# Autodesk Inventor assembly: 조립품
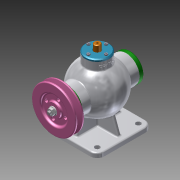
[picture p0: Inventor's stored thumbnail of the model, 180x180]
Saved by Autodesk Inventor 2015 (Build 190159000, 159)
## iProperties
Created: 2025-08
Part Number: 조립품
Document SubType Name: Assembly
Designer: USER
Author: USER
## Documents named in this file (15)
- C:\Users\USER\Downloads\750808V1013\답안조립품.iam
- C:\Users\USER\Downloads\750808V1013\본체.ipt
- C:\Users\USER\Downloads\750808V1013\가져온 구성요소\V-벨트풀리\V-벨트풀리.ipt
- C:\Users\USER\Downloads\750808V1013\가져온 구성요소\너트 M8\너트 M8.ipt
- C:\Users\USER\Downloads\750808V1013\가져온 구성요소\뒤커버\뒤커버.ipt
- C:\Users\USER\Downloads\750808V1013\가져온 구성요소\베어링- 6202\베어링- 6202.ipt
- C:\Users\USER\Downloads\750808V1013\가져온 구성요소\볼트 M4 x 12\볼트 M4 x 12.ipt
- C:\Users\USER\Downloads\750808V1013\가져온 구성요소\볼트 M4 x 16\볼트 M4 x 16.ipt
- C:\Users\USER\Downloads\750808V1013\가져온 구성요소\상부커버\상부커버.ipt
- C:\Users\USER\Downloads\750808V1013\가져온 구성요소\슬라이드\슬라이드.ipt
- C:\Users\USER\Downloads\750808V1013\가져온 구성요소\앞커버\앞커버.ipt
- C:\Users\USER\Downloads\750808V1013\가져온 구성요소\오일실 15 30 7\오일실 15 30 7.ipt
- C:\Users\USER\Downloads\750808V1013\가져온 구성요소\칼라\칼라.ipt
- C:\Users\USER\Downloads\750808V1013\가져온 구성요소\키 4 x 4 x 12\키 4 x 4 x 12.ipt
- C:\Users\USER\Downloads\750808V1013\가져온 구성요소\편심축\편심축.ipt
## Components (1 placed, 1 different names)
1. V-벨트풀리:1
